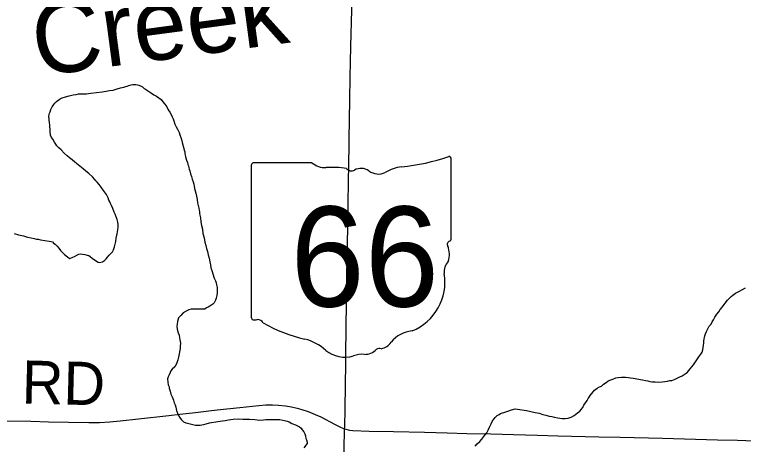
# Model space of a CAD drawing. Extents: x 0 to 34, y 0 to 22.
# Drawn here: x 27.345 to 28.306, y 15.328 to 15.894 of the extents above; entities that cross this region are included whole.
import ezdxf

# ---------------------------------------------------------------- set-up
doc = ezdxf.new("R2010")
doc.units = 0
for name, color, linetype in [('GM_X_County_Road', 7, 'Continuous'), ('GM_X_County_Road_Text', 7, 'Continuous'), ('GM_X_Minor_River', 7, 'Continuous'), ('GM_X_Minor_River_Text', 7, 'Continuous'), ('GM_X_State_Route', 7, 'Continuous'), ('GM_X_State_Shield', 7, 'Continuous')]:
    doc.layers.add(name, color=color, linetype=linetype)

msp = doc.modelspace()

# ---------------------------------------------------------------- linework, layer by layer
at = {"layer": 'GM_X_County_Road'}
for points in [[(27.6012, 15.37192), (27.61236, 15.37321), (27.64201, 15.37651), (27.66733, 15.37908), (27.67659, 15.37971), (27.68522, 15.37986), (27.69324, 15.37947), (27.70245, 15.37848), (27.71038, 15.37718), (27.71761, 15.37561), (27.72414, 15.37377), (27.73232, 15.37095), (27.74151, 15.36728), (27.7488, 15.36392), (27.76695, 15.3544), (27.77592, 15.34999), (27.78042, 15.34806)], [(27.26997, 15.35976), (27.29871, 15.35925), (27.32978, 15.35871), (27.36644, 15.35821), (27.39005, 15.35756), (27.41615, 15.35698), (27.4429, 15.35651), (27.45723, 15.35679), (27.47091, 15.35757), (27.48455, 15.35879), (27.50866, 15.36141), (27.54876, 15.36591), (27.56295, 15.36752), (27.58395, 15.36993), (27.6012, 15.37192)], [(27.78042, 15.34806), (27.78676, 15.34643), (27.79117, 15.34605), (27.81296, 15.34536), (27.84465, 15.34473), (27.88566, 15.34371), (27.91548, 15.34282), (27.94159, 15.3422), (27.97329, 15.34151), (28.00311, 15.34074), (28.0348, 15.34005), (28.06151, 15.33924), (28.11557, 15.33794), (28.14355, 15.33731), (28.19947, 15.33586), (28.24297, 15.3347), (28.27218, 15.33398), (28.29827, 15.33321), (28.32063, 15.3323)]]:
    msp.add_lwpolyline(points, dxfattribs=at)
at = {"layer": 'GM_X_Minor_River'}
for points in [[(27.45928, 15.6668), (27.45669, 15.67028), (27.45409, 15.67338), (27.45222, 15.67495), (27.45112, 15.67688), (27.44777, 15.68038), (27.44329, 15.68466), (27.43917, 15.6878), (27.43543, 15.69093), (27.42457, 15.69955), (27.4212, 15.70266), (27.41746, 15.70541), (27.41447, 15.70814), (27.41074, 15.71165), (27.40664, 15.71593), (27.40365, 15.71866), (27.40103, 15.72101), (27.39956, 15.72332), (27.39771, 15.72603), (27.39551, 15.72988), (27.39403, 15.7322), (27.39258, 15.73528), (27.3923, 15.74023), (27.39199, 15.74329), (27.39167, 15.74634), (27.39172, 15.74862), (27.39103, 15.75206), (27.39072, 15.75512), (27.39076, 15.75702), (27.39044, 15.76007), (27.39087, 15.76234), (27.39129, 15.76424), (27.3921, 15.76613), (27.39292, 15.76915), (27.3949, 15.77253), (27.39686, 15.77554), (27.39805, 15.77742), (27.40038, 15.77965), (27.40386, 15.78224), (27.40657, 15.78408), (27.41232, 15.78586), (27.4173, 15.78727), (27.42227, 15.7883), (27.42647, 15.78897), (27.42953, 15.78966), (27.43258, 15.78959), (27.43639, 15.78989), (27.43982, 15.78981), (27.44249, 15.79013), (27.44555, 15.79045), (27.46082, 15.79239), (27.46578, 15.79305), (27.47038, 15.79409), (27.47534, 15.79474), (27.48032, 15.79615), (27.48492, 15.79757), (27.48913, 15.79862), (27.49181, 15.79932), (27.49372, 15.79966), (27.49603, 15.80075), (27.49909, 15.80145), (27.50101, 15.80216), (27.5033, 15.80211), (27.5052, 15.80207), (27.50709, 15.80165), (27.50899, 15.80123), (27.51201, 15.80002), (27.51389, 15.79883), (27.51613, 15.79688), (27.51801, 15.7957), (27.52026, 15.79412), (27.52289, 15.79254), (27.5259, 15.79057), (27.5289, 15.7886), (27.53229, 15.78662), (27.53528, 15.78427), (27.53829, 15.7823), (27.54051, 15.77921), (27.54349, 15.77609), (27.54608, 15.77261), (27.54752, 15.76877), (27.55012, 15.76567), (27.55157, 15.76259), (27.55303, 15.75951), (27.5545, 15.75682), (27.5552, 15.75413), (27.55664, 15.74991), (27.55846, 15.74607), (27.55992, 15.74299), (27.56211, 15.73875), (27.56319, 15.73568), (27.56426, 15.73223), (27.56534, 15.72954), (27.56602, 15.72572), (27.56851, 15.71767), (27.56885, 15.71538), (27.56957, 15.71346), (27.56989, 15.71079), (27.57058, 15.70735), (27.57091, 15.70506), (27.572, 15.70237)], [(27.572, 15.70237), (27.57307, 15.6993), (27.57378, 15.69662), (27.5745, 15.6947), (27.57483, 15.69241), (27.57555, 15.69048), (27.57626, 15.68819), (27.57732, 15.68436), (27.57839, 15.68091), (27.57946, 15.67746), (27.58052, 15.67363), (27.5816, 15.67056), (27.58192, 15.66788), (27.58263, 15.6652), (27.58332, 15.66176), (27.58401, 15.6587), (27.58507, 15.65487), (27.58575, 15.65067), (27.58641, 15.64608), (27.58748, 15.64263), (27.58817, 15.63919), (27.58849, 15.63652), (27.58883, 15.63461), (27.58917, 15.6327), (27.58949, 15.62965), (27.59017, 15.6262), (27.59083, 15.62124), (27.59186, 15.61627), (27.5929, 15.6113), (27.59354, 15.60557), (27.59532, 15.59982), (27.59597, 15.59448), (27.59739, 15.58988), (27.59846, 15.58605), (27.59951, 15.58184), (27.60056, 15.57762), (27.6016, 15.57303), (27.60265, 15.56844), (27.60333, 15.56462), (27.604, 15.56042), (27.60507, 15.55697), (27.60828, 15.547), (27.61011, 15.54315), (27.61081, 15.54047), (27.61152, 15.53817), (27.61221, 15.53473), (27.61253, 15.53206), (27.61245, 15.52787), (27.61199, 15.52407), (27.61114, 15.52028), (27.61032, 15.51764), (27.60835, 15.51425), (27.6064, 15.51239), (27.60254, 15.50981), (27.60023, 15.50872), (27.5983, 15.50762), (27.59599, 15.50615), (27.59408, 15.50581), (27.59103, 15.50588), (27.58837, 15.50594), (27.58532, 15.50601), (27.58266, 15.50607), (27.58, 15.50613), (27.57809, 15.50617), (27.57502, 15.50509), (27.57156, 15.50327), (27.5677, 15.50107), (27.5642, 15.49772), (27.56146, 15.49435), (27.55985, 15.48982), (27.55939, 15.48641), (27.55932, 15.48336), (27.55963, 15.47955), (27.56067, 15.47496), (27.56212, 15.4715), (27.56243, 15.46806), (27.56314, 15.46577), (27.56347, 15.46347), (27.56418, 15.46117), (27.56372, 15.45738), (27.56365, 15.45395), (27.5615, 15.44258), (27.56029, 15.43918), (27.55865, 15.43388), (27.55629, 15.43013), (27.55279, 15.42678), (27.55122, 15.42491), (27.55041, 15.42265), (27.5492, 15.41925), (27.54762, 15.41662), (27.5468, 15.41397), (27.54747, 15.40977), (27.54778, 15.40633), (27.54887, 15.40365), (27.54921, 15.40173), (27.55027, 15.3979), (27.55133, 15.39407), (27.55278, 15.39061), (27.55387, 15.38831), (27.55458, 15.38601), (27.55565, 15.38256)], [(27.3445, 15.60576), (27.35056, 15.6041), (27.357, 15.60244), (27.36229, 15.6008), (27.36722, 15.59993), (27.37101, 15.59908), (27.37404, 15.59825), (27.37633, 15.5982), (27.37935, 15.59738), (27.39074, 15.5956), (27.3934, 15.59516), (27.39529, 15.59474), (27.39639, 15.59281), (27.39865, 15.59162), (27.40126, 15.58889), (27.4035, 15.58656), (27.40571, 15.58347), (27.40907, 15.57996), (27.41093, 15.57802), (27.41281, 15.57684), (27.41542, 15.57449), (27.41806, 15.57291), (27.42189, 15.57435), (27.4242, 15.57544), (27.42729, 15.57728), (27.42998, 15.57836), (27.43227, 15.57869), (27.43455, 15.57864), (27.43797, 15.57818), (27.44099, 15.57697), (27.44289, 15.57655), (27.44476, 15.57537), (27.44775, 15.57264), (27.45527, 15.5679), (27.45716, 15.56748), (27.46099, 15.56853), (27.46369, 15.57), (27.46602, 15.57223), (27.46759, 15.57448), (27.46993, 15.57709), (27.4715, 15.57896), (27.47422, 15.58157), (27.47542, 15.5842), (27.47702, 15.58798), (27.47786, 15.59176), (27.4787, 15.59517), (27.47917, 15.59935), (27.48044, 15.60541), (27.48131, 15.61034), (27.48177, 15.61414), (27.48184, 15.61756), (27.48153, 15.62062), (27.48046, 15.62407), (27.47901, 15.62753), (27.47794, 15.63098), (27.47647, 15.63367), (27.47468, 15.63866), (27.47285, 15.64251), (27.47177, 15.6452), (27.47068, 15.64751), (27.46958, 15.64981), (27.4685, 15.65288), (27.46631, 15.65712), (27.46262, 15.66253), (27.45928, 15.6668)], [(28.16106, 15.4152), (28.17319, 15.41264), (28.17698, 15.4118), (28.1804, 15.41134), (28.18267, 15.41053), (28.18571, 15.41008), (28.1899, 15.41037), (28.19484, 15.40988), (28.19904, 15.41017), (28.20247, 15.41047), (28.20629, 15.41115), (28.20935, 15.41184), (28.21164, 15.41217), (28.21394, 15.41288), (28.21625, 15.41359), (28.21894, 15.41506), (28.22241, 15.41688), (28.22549, 15.41834), (28.22934, 15.42054), (28.23244, 15.42313), (28.23596, 15.42724), (28.24026, 15.43248), (28.2438, 15.43773), (28.24734, 15.44298), (28.25008, 15.44673), (28.25166, 15.44935), (28.25287, 15.45237), (28.25331, 15.45541), (28.25376, 15.45845), (28.2542, 15.4611), (28.25425, 15.46376), (28.2547, 15.4668), (28.25512, 15.46869), (28.25555, 15.47097), (28.25637, 15.47361), (28.25757, 15.47663), (28.25917, 15.48002), (28.26115, 15.48379), (28.2635, 15.4864), (28.26508, 15.48941), (28.26666, 15.49204), (28.26864, 15.49542), (28.271, 15.49918), (28.27374, 15.50255), (28.27571, 15.50555), (28.27845, 15.50891), (28.2808, 15.51191), (28.28236, 15.51377), (28.28511, 15.5179), (28.29017, 15.52274), (28.29249, 15.52459), (28.29597, 15.52718), (28.30021, 15.52937), (28.30483, 15.53193), (28.30907, 15.53412)], [(27.95237, 15.32541), (27.9551, 15.3284), (27.9586, 15.33174), (27.96133, 15.33473), (27.96525, 15.33997), (27.96798, 15.34296), (27.96957, 15.34635), (27.97157, 15.35049), (27.97357, 15.35502), (27.97555, 15.35878), (27.97751, 15.3614), (27.97907, 15.36327), (27.98141, 15.36588), (27.98411, 15.36734), (27.98604, 15.36845), (27.98835, 15.36954), (27.99026, 15.36988), (27.99409, 15.37093), (27.99678, 15.37201), (28.00024, 15.37346), (28.00521, 15.37449), (28.0204, 15.37263), (28.02608, 15.37098), (28.03176, 15.36972), (28.03707, 15.36884), (28.04161, 15.36721), (28.04578, 15.36636), (28.04994, 15.36513), (28.05374, 15.36466), (28.05676, 15.36345), (28.06131, 15.36259), (28.06435, 15.36214), (28.06739, 15.36169), (28.0712, 15.36199), (28.07501, 15.36228), (28.07923, 15.36371), (28.08309, 15.36591), (28.08735, 15.36924), (28.09044, 15.37146), (28.09239, 15.3737), (28.09435, 15.37632), (28.09594, 15.37933), (28.09792, 15.38272), (28.10027, 15.38571), (28.10147, 15.38835), (28.10303, 15.39021), (28.10421, 15.39209), (28.10578, 15.39434), (28.10851, 15.39733), (28.11007, 15.3992), (28.11318, 15.40179), (28.11626, 15.40363), (28.11895, 15.40471), (28.12166, 15.40693), (28.12515, 15.40952), (28.12746, 15.41099), (28.13016, 15.41246), (28.134, 15.41389), (28.13784, 15.41533), (28.14128, 15.41602), (28.14547, 15.4163), (28.14852, 15.41624), (28.1508, 15.41619), (28.15423, 15.41611), (28.15726, 15.41566), (28.16106, 15.4152)], [(27.55565, 15.38256), (27.55674, 15.37987), (27.55781, 15.3768), (27.55886, 15.37259), (27.55993, 15.36876), (27.56175, 15.36491), (27.56359, 15.3622), (27.56508, 15.36027), (27.56806, 15.35754), (27.57109, 15.35633), (27.57336, 15.35589), (27.57676, 15.35468), (27.58017, 15.35384), (27.58358, 15.353), (27.58701, 15.35293), (27.59006, 15.35324), (27.59197, 15.35358), (27.59464, 15.3539), (27.59771, 15.35498), (27.6023, 15.35602), (27.61301, 15.35806), (27.61606, 15.35838), (27.6195, 15.35868), (27.62294, 15.35936), (27.62714, 15.36003), (27.63326, 15.36104), (27.64011, 15.36127), (27.64621, 15.36113), (27.65077, 15.36103), (27.65496, 15.36094), (27.6618, 15.36041), (27.66827, 15.35988), (27.67322, 15.36015), (27.67628, 15.36047), (27.67894, 15.36041), (27.68314, 15.3607), (27.68884, 15.36057), (27.69265, 15.36048), (27.69493, 15.36043), (27.6991, 15.35958), (27.701, 15.35916), (27.70441, 15.35832), (27.70706, 15.3575), (27.71082, 15.35551), (27.71573, 15.3535), (27.71912, 15.3519), (27.72101, 15.3511), (27.72287, 15.34915), (27.72435, 15.34684), (27.72657, 15.34412), (27.72805, 15.34181), (27.72875, 15.33913), (27.72944, 15.33568), (27.73016, 15.33376), (27.73085, 15.3307), (27.7312, 15.32879), (27.72651, 15.32319)]]:
    msp.add_lwpolyline(points, dxfattribs=at)
at = {"layer": 'GM_X_State_Route'}
for p, q in [((27.78282, 15.50499), (27.78329, 15.53538)), ((27.7828, 15.50397), (27.78282, 15.50499))]:
    msp.add_line(p, q, dxfattribs=at)
for points in [[(27.7865, 15.73023), (27.78704, 15.78187), (27.78757, 15.81168), (27.78866, 15.85205), (27.79008, 15.9005), (27.7917, 15.95142), (27.79259, 15.98186), (27.79405, 16.03404), (27.79528, 16.07752), (27.79659, 16.12597), (27.79735, 16.15578), (27.79936, 16.21602), (27.80068, 16.26074), (27.80125, 16.2796), (27.80179, 16.29739), (27.8037, 16.36074), (27.80496, 16.38756)], [(27.78518, 15.64589), (27.78519, 15.64688), (27.78549, 15.67248), (27.78645, 15.72204), (27.7865, 15.73023)], [(27.78329, 15.53538), (27.78346, 15.54843), (27.78429, 15.59703), (27.78486, 15.62194), (27.78518, 15.64589)], [(27.78042, 15.34806), (27.78049, 15.35069), (27.781, 15.37494), (27.78184, 15.43524), (27.78261, 15.49182), (27.7828, 15.50397)], [(27.77733, 15.2243), (27.77753, 15.23448), (27.77834, 15.26492), (27.77929, 15.29911), (27.77968, 15.32087), (27.78042, 15.34806)]]:
    msp.add_lwpolyline(points, dxfattribs=at)
at = {"layer": 'GM_X_State_Shield'}
for p, q in [((27.65731, 15.69541), (27.65731, 15.49528)), ((27.73712, 15.69885), (27.65991, 15.69885)), ((27.92098, 15.59912), (27.92098, 15.70381)), ((27.92095, 15.59915), (27.92098, 15.59912))]:
    msp.add_line(p, q, dxfattribs=at)
for centre, radius, start, end in [((27.82706, 15.97168), 0.27962, 275.84447, 288.90645), ((27.91805, 15.70424), 0.00294, 351.86209, 97.738), ((27.66033, 15.69583), 0.00305, 98.1301, 188.1301), ((27.75551, 15.72208), 0.02963, 231.61951, 271.11188), ((27.76534, 15.5865), 0.10636, 80.48669, 94.98827), ((27.78948, 15.69687), 0.00855, 219.79206, 297.10237), ((27.80203, 15.67374), 0.01777, 54.46668, 119.14113), ((27.82497, 15.70546), 0.02138, 233.85621, 294.82819), ((27.86272, 15.63773), 0.05625, 97.34618, 120.76885), ((27.91785, 15.59872), 0.00314, 289.60381, 7.73413), ((27.9203, 15.59144), 0.00454, 107.94398, 210.33697), ((27.8914, 15.5782), 0.02727, 340.03296, 23.64957), ((27.9315, 15.55531), 0.01984, 136.8065, 186.92959), ((27.84272, 15.542), 0.06994, 292.30889, 8.98584), ((27.66036, 15.49485), 0.00308, 171.95839, 258.30661), ((27.66083, 15.51532), 0.02352, 267.33899, 280.60386), ((27.66564, 15.48374), 0.00848, 29.74838, 93.27175), ((27.7727, 15.66354), 0.20192, 240.41292, 257.1985), ((27.87221, 15.4391), 0.0383, 94.40312, 142.57675), ((27.7125, 15.40538), 0.06318, 47.18416, 75.83597), ((27.82624, 15.44838), 0.00601, 65.75173, 132.64842), ((27.82368, 15.47589), 0.0226, 282.87319, 323.27711), ((27.78083, 15.48275), 0.04009, 230.70037, 286.29184), ((27.80399, 15.41356), 0.03294, 85.69512, 111.20995), ((27.80692, 15.46776), 0.02136, 268.77702, 315.54927)]:
    msp.add_arc(centre, radius, start, end, dxfattribs=at)

# ---------------------------------------------------------------- texts
at = {"layer": 'GM_X_County_Road_Text'}
msp.add_text('RD', height=0.056818, rotation=358.57294, dxfattribs=at).set_placement((27.35414, 15.38175))
at = {"layer": 'GM_X_Minor_River_Text'}
msp.add_text('Creek', height=0.094744, rotation=7.62383, dxfattribs=at).set_placement((27.37468, 15.81261))
at = {"layer": 'GM_X_State_Shield'}
msp.add_text('66', height=0.131836, dxfattribs=at).set_placement((27.70884, 15.5094))

doc.saveas('drawing.dxf')
